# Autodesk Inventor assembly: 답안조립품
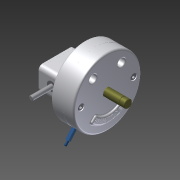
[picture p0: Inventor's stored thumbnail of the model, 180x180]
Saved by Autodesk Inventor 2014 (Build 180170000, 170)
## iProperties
Created: 2015-04
Part Number: 답안조립품
Document SubType Name: Assembly
Designer: Administrator
Author: Administrator
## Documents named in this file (15)
- C:\Documents and Settings\Administrator\바탕 화면\350406V1020\답안조립품.iam
- C:\Documents and Settings\Administrator\바탕 화면\350406V1020\본체.ipt
- C:\Documents and Settings\Administrator\바탕 화면\350406V1020\커버.ipt
- C:\Documents and Settings\Administrator\바탕 화면\350406V1020\커버2.ipt
- C:\Documents and Settings\Administrator\바탕 화면\350406V1020\M 10 x 35.ipt
- C:\Documents and Settings\Administrator\바탕 화면\350406V1020\M 5 x 12.ipt
- C:\Documents and Settings\Administrator\바탕 화면\350406V1020\부시.ipt
- C:\Documents and Settings\Administrator\바탕 화면\350406V1020\베어링62_22.ipt
- C:\Documents and Settings\Administrator\바탕 화면\350406V1020\축.ipt
- C:\Documents and Settings\Administrator\바탕 화면\350406V1020\멈춤링.ipt
- C:\Documents and Settings\Administrator\바탕 화면\350406V1020\가변 스프링.ipt
- C:\Documents and Settings\Administrator\바탕 화면\350406V1020\슬라이더2.ipt
- C:\Documents and Settings\Administrator\바탕 화면\350406V1020\슬라이더.ipt
- C:\Documents and Settings\Administrator\바탕 화면\350406V1020\평행핀.ipt
- C:\Documents and Settings\Administrator\바탕 화면\350406V1020\슬라이더3.ipt
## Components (6 placed, 4 different names)
1. M 10 x 35:1
2. M 10 x 35:2
3. M 5 x 12:1
4. M 5 x 12:2
5. KS B 1320 B B 5 x  20:1 — 플러쉬:2
6. 가변 스프링:1
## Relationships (1: Flush 1)
- 플러쉬:2 [Flush]: KS B 1320 B B 5 x  20:1
